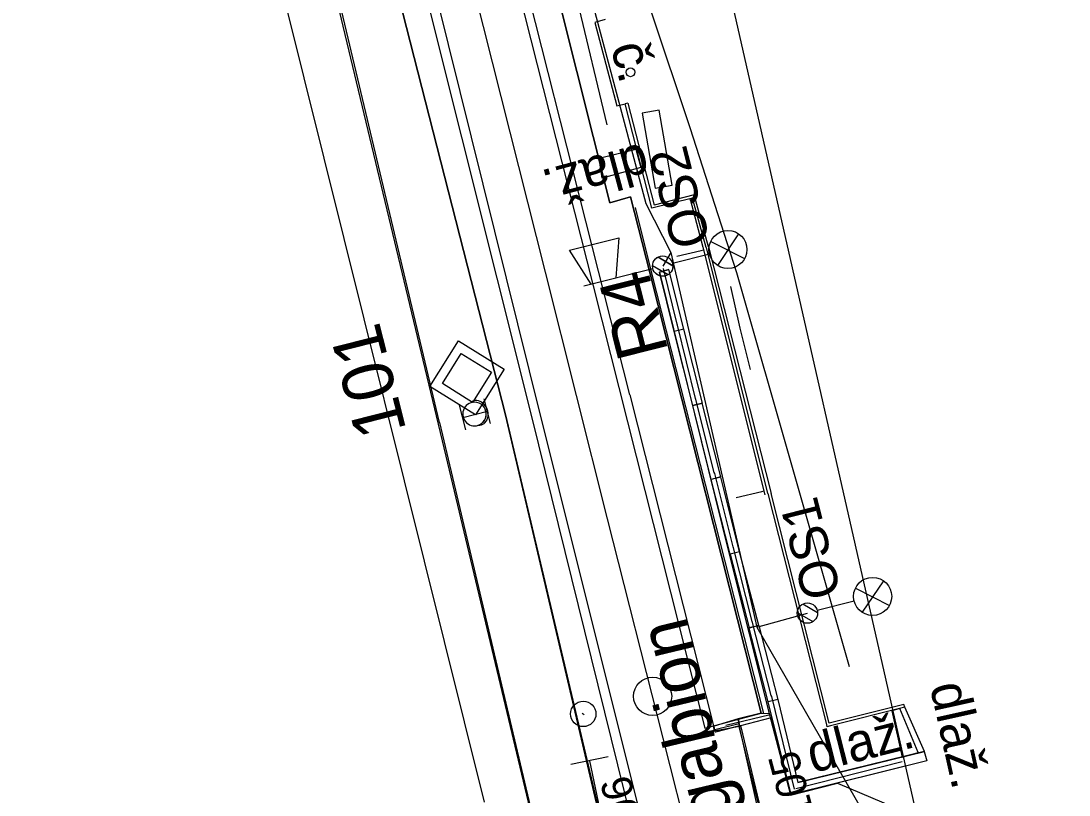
# Model space of a CAD drawing. Extents: x -754679 to -754173, y -1169241 to -1168288.
# Drawn here: x -754414.28 to -754373.05, y -1168944.54 to -1168914.1 of the extents above; entities that cross this region are included whole.
import ezdxf

# ---------------------------------------------------------------- set-up
doc = ezdxf.new("R2010")
doc.units = 0
for name, color, linetype in [('Vrstva 1', 7, 'Continuous'), ('Vrstva 11', 7, 'Continuous'), ('Vrstva 12', 7, 'Continuous'), ('Vrstva 13', 7, 'Continuous'), ('Vrstva 14', 7, 'Continuous'), ('Vrstva 16', 7, 'Continuous'), ('Vrstva 17', 7, 'Continuous'), ('Vrstva 23', 7, 'Continuous'), ('Vrstva 25', 7, 'Continuous'), ('Vrstva 31', 7, 'Continuous'), ('Vrstva 33', 7, 'Continuous'), ('Vrstva 4', 7, 'Continuous'), ('Vrstva 43', 7, 'Continuous'), ('Vrstva 49', 7, 'Continuous'), ('Vrstva 51', 7, 'Continuous'), ('Vrstva 53', 7, 'Continuous'), ('Vrstva 59', 7, 'Continuous'), ('Vrstva 6', 7, 'Continuous'), ('Vrstva 60', 7, 'Continuous'), ('Vrstva 7', 7, 'Continuous')]:
    doc.layers.add(name, color=color, linetype=linetype)

msp = doc.modelspace()

# ---------------------------------------------------------------- linework, layer by layer
at = {"layer": 'Vrstva 1'}
msp.add_lwpolyline([(-754384.656, -1168959.571), (-754385.936, -1168954.491), (-754386.734, -1168951.322), (-754387.865, -1168946.893), (-754387.928, -1168946.598), (-754389.016, -1168942.293), (-754391.2, -1168933.67), (-754393.647, -1168923.979), (-754396.084, -1168914.315), (-754398.294, -1168905.574)], dxfattribs=at)
at = {"layer": 'Vrstva 11'}
for p, q in [((-754395.81, -1168929.924), (-754396.055, -1168928.955)), ((-754396.779, -1168930.169), (-754397.024, -1168929.2)), ((-754396.902, -1168929.685), (-754395.932, -1168929.439))]:
    msp.add_line(p, q, dxfattribs=at)
at = {"layer": 'Vrstva 12'}
for p, q in [((-754396.521, -1168929.047), (-754396.519, -1168929.099)), ((-754395.985, -1168929.451), (-754395.912, -1168929.468)), ((-754396.315, -1168930.002), (-754396.285, -1168929.991))]:
    msp.add_line(p, q, dxfattribs=at)
for centre, major_axis, ratio, start_param, end_param in [((-754396.437, -1168929.555), (-0.102, 0.452), 0.999997, 6.240007, 10.999586), ((-754396.328, -1168929.506), (-0.199, 0.457), 0.826527, 2.759103, 6.267517), ((-754396.437, -1168929.555), (-0.102, 0.452), 0.999997, 3.184771, 6.240007)]:
    msp.add_ellipse(centre, major_axis=major_axis, ratio=ratio, start_param=start_param, end_param=end_param, dxfattribs=at)
at = {"layer": 'Vrstva 13'}
for p, q in [((-754388.795, -1168923.864), (-754389.165, -1168923.968)), ((-754388.582, -1168926.306), (-754389.165, -1168923.968)), ((-754389.165, -1168923.968), (-754389.161, -1168923.973)), ((-754389.161, -1168923.973), (-754388.795, -1168923.864)), ((-754389.161, -1168923.973), (-754386.419, -1168935.058)), ((-754388.209, -1168926.212), (-754388.795, -1168923.864)), ((-754388.795, -1168923.864), (-754388.795, -1168923.864)), ((-754388.209, -1168926.212), (-754388.582, -1168926.306)), ((-754388.207, -1168926.214), (-754388.582, -1168926.307)), ((-754388.582, -1168926.307), (-754388.582, -1168926.306)), ((-754387.853, -1168929.212), (-754388.582, -1168926.307)), ((-754388.207, -1168926.214), (-754388.209, -1168926.212)), ((-754387.475, -1168929.122), (-754388.207, -1168926.214)), ((-754387.475, -1168929.122), (-754387.853, -1168929.212)), ((-754387.853, -1168929.212), (-754387.481, -1168929.123)), ((-754387.481, -1168929.123), (-754387.475, -1168929.122)), ((-754386.748, -1168932.026), (-754387.481, -1168929.123)), ((-754387.123, -1168932.124), (-754387.853, -1168929.212)), ((-754387.853, -1168929.212), (-754387.853, -1168929.212)), ((-754386.748, -1168932.026), (-754387.123, -1168932.124)), ((-754386.75, -1168932.032), (-754387.122, -1168932.123)), ((-754386.75, -1168932.032), (-754386.748, -1168932.026)), ((-754386.01, -1168934.971), (-754386.75, -1168932.032)), ((-754387.122, -1168932.123), (-754387.123, -1168932.124)), ((-754386.387, -1168935.069), (-754387.122, -1168932.123)), ((-754386.419, -1168935.058), (-754384.844, -1168941.33)), ((-754386.009, -1168934.97), (-754386.387, -1168935.07)), ((-754386.01, -1168934.971), (-754386.387, -1168935.069)), ((-754386.387, -1168935.07), (-754386.387, -1168935.069)), ((-754386.387, -1168935.07), (-754385.634, -1168937.967)), ((-754386.009, -1168934.97), (-754386.01, -1168934.971)), ((-754385.256, -1168937.865), (-754386.009, -1168934.97)), ((-754385.256, -1168937.865), (-754385.634, -1168937.967)), ((-754385.631, -1168937.968), (-754385.634, -1168937.967)), ((-754385.256, -1168937.866), (-754385.631, -1168937.968)), ((-754384.889, -1168940.869), (-754385.631, -1168937.968)), ((-754385.256, -1168937.866), (-754385.256, -1168937.865)), ((-754385.256, -1168937.866), (-754384.511, -1168940.778)), ((-754384.51, -1168940.78), (-754384.892, -1168940.869)), ((-754383.981, -1168944.518), (-754384.892, -1168940.869)), ((-754384.892, -1168940.869), (-754384.889, -1168940.869)), ((-754384.511, -1168940.778), (-754384.889, -1168940.869)), ((-754384.51, -1168940.78), (-754384.511, -1168940.778)), ((-754384.511, -1168940.778), (-754383.714, -1168944.039)), ((-754384.51, -1168940.78), (-754383.714, -1168944.04)), ((-754386.071, -1168941.545), (-754387.015, -1168941.827)), ((-754386.008, -1168941.815), (-754386.071, -1168941.545)), ((-754385.963, -1168941.8), (-754384.759, -1168941.493)), ((-754384.844, -1168941.33), (-754384.011, -1168944.533)), ((-754384.759, -1168941.493), (-754384.006, -1168944.538)), ((-754386.97, -1168942.062), (-754387.015, -1168941.827)), ((-754386.027, -1168941.732), (-754386.979, -1168941.973)), ((-754386.008, -1168941.815), (-754386.97, -1168942.062)), ((-754386.027, -1168941.731), (-754386.027, -1168941.732)), ((-754386.007, -1168941.817), (-754386.027, -1168941.732)), ((-754386.023, -1168941.847), (-754385.963, -1168941.8)), ((-754385.064, -1168945.684), (-754386.023, -1168941.847)), ((-754386.008, -1168941.815), (-754386.007, -1168941.817)), ((-754385.032, -1168945.69), (-754385.963, -1168941.8)), ((-754386.96, -1168942.06), (-754386.979, -1168941.973)), ((-754378.65, -1168943.193), (-754384.011, -1168944.533)), ((-754378.643, -1168943.195), (-754383.981, -1168944.518)), ((-754383.714, -1168944.039), (-754378.74, -1168942.822)), ((-754378.748, -1168942.827), (-754383.714, -1168944.04)), ((-754378.748, -1168942.827), (-754378.74, -1168942.822)), ((-754378.748, -1168942.827), (-754378.643, -1168943.195)), ((-754378.643, -1168943.195), (-754378.65, -1168943.193)), ((-754383.714, -1168944.04), (-754383.714, -1168944.039)), ((-754383.981, -1168944.518), (-754384.011, -1168944.533))]:
    msp.add_line(p, q, dxfattribs=at)
for points in [[(-754386.027, -1168941.731), (-754386.982, -1168941.97), (-754386.979, -1168941.973)], [(-754386.007, -1168941.817), (-754386.96, -1168942.06), (-754386.97, -1168942.062)]]:
    msp.add_lwpolyline(points, dxfattribs=at)
at = {"layer": 'Vrstva 14'}
for p, q in [((-754391.113, -1168921.242), (-754393.063, -1168913.475)), ((-754390.299, -1168921.015), (-754391.113, -1168921.242)), ((-754389.528, -1168924.038), (-754390.299, -1168921.015)), ((-754385.162, -1168941.315), (-754389.528, -1168924.038)), ((-754387.375, -1168941.909), (-754385.162, -1168941.315))]:
    msp.add_line(p, q, dxfattribs=at)
msp.add_lwpolyline([(-754414.276, -1168835.483), (-754412.566, -1168842.248), (-754407.917, -1168860.63), (-754403.513, -1168878.067), (-754399.115, -1168895.474), (-754395.207, -1168910.943), (-754391.772, -1168924.511), (-754387.375, -1168941.909)], dxfattribs=at)
at = {"layer": 'Vrstva 16'}
for p, q in [((-754402.14, -1168902.474), (-754395.222, -1168929.578)), ((-754397.82, -1168929.888), (-754404.14, -1168903.209)), ((-754390.209, -1168950.962), (-754395.222, -1168929.578)), ((-754397.82, -1168929.888), (-754393.322, -1168948.872))]:
    msp.add_line(p, q, dxfattribs=at)
msp.add_lwpolyline([(-754391.54, -1168919.494), (-754390.097, -1168919.138), (-754389.895, -1168919.863), (-754391.413, -1168920.273), (-754391.54, -1168919.494)], dxfattribs=at)
at = {"layer": 'Vrstva 17'}
for p, q in [((-754384.808, -1168941.38), (-754386.547, -1168941.8)), ((-754379.619, -1168943.23), (-754383.796, -1168944.293))]:
    msp.add_line(p, q, dxfattribs=at)
msp.add_lwpolyline([(-754383.844, -1168944.301), (-754384.743, -1168940.667), (-754384.765, -1168940.627), (-754385.496, -1168937.745), (-754385.514, -1168937.714), (-754386.249, -1168934.81), (-754386.265, -1168934.776), (-754386.989, -1168931.888), (-754387.01, -1168931.853), (-754387.726, -1168928.979), (-754387.745, -1168928.942), (-754388.446, -1168926.057), (-754388.467, -1168926.021), (-754388.997, -1168923.827)], dxfattribs=at)
at = {"layer": 'Vrstva 23'}
msp.add_line((-754391.701, -1168914.153), (-754390.842, -1168917.432), dxfattribs=at)
for points in [[(-754381.681, -1168939.489), (-754386.122, -1168924.006), (-754387.953, -1168918.303), (-754395.607, -1168895.383), (-754402.869, -1168866.173)], [(-754393.344, -1168948.888), (-754397.546, -1168931.205), (-754401.742, -1168913.695), (-754408.583, -1168884.482)], [(-754386.365, -1168924.542), (-754385.996, -1168926.171), (-754385.598, -1168927.803)]]:
    msp.add_lwpolyline(points, dxfattribs=at)
msp.add_lwpolyline([(-754389.177, -1168917.603), (-754389.843, -1168917.719), (-754389.331, -1168920.671), (-754388.665, -1168920.555)], close=True, dxfattribs=at)
at = {"layer": 'Vrstva 25'}
for p, q in [((-754386.047, -1168922.471), (-754386.881, -1168923.707)), ((-754387.138, -1168922.762), (-754385.811, -1168923.442)), ((-754389.208, -1168923.377), (-754388.638, -1168923.717)), ((-754387.193, -1168923.27), (-754388.647, -1168923.637)), ((-754389.43, -1168923.71), (-754388.823, -1168924.072)), ((-754380.356, -1168936.113), (-754381.19, -1168937.349)), ((-754381.448, -1168936.405), (-754380.12, -1168937.083)), ((-754383.517, -1168937.022), (-754382.947, -1168937.361)), ((-754381.502, -1168936.913), (-754382.956, -1168937.281)), ((-754383.739, -1168937.354), (-754383.132, -1168937.716))]:
    msp.add_line(p, q, dxfattribs=at)
for points in [[(-754392.606, -1168910.34), (-754389.7, -1168921.276), (-754388.719, -1168923.201), (-754389.035, -1168923.735)], [(-754388.719, -1168923.201), (-754385.337, -1168937.932), (-754383.344, -1168937.379)], [(-754385.337, -1168937.932), (-754380.924, -1168945.594), (-754378.67, -1168951.057), (-754378.525, -1168951.376)]]:
    msp.add_lwpolyline(points, dxfattribs=at)
for centre, radius in [((-754386.468, -1168923.084), 0.749), ((-754389.035, -1168923.735), 0.4), ((-754380.777, -1168936.726), 0.749), ((-754383.344, -1168937.379), 0.4)]:
    msp.add_circle(centre, radius, dxfattribs=at)
at = {"layer": 'Vrstva 31'}
for points in [[(-754392.606, -1168910.34), (-754389.7, -1168921.276), (-754388.719, -1168923.201), (-754389.035, -1168923.735)], [(-754388.719, -1168923.201), (-754385.337, -1168937.932), (-754380.924, -1168945.594), (-754378.67, -1168951.057), (-754378.525, -1168951.376)]]:
    msp.add_lwpolyline(points, dxfattribs=at)
at = {"layer": 'Vrstva 33'}
for p, q in [((-754388.637, -1168923.732), (-754389.222, -1168923.383)), ((-754392.134, -1168924.517), (-754389.423, -1168923.833)), ((-754388.834, -1168924.08), (-754389.432, -1168923.724))]:
    msp.add_line(p, q, dxfattribs=at)
msp.add_lwpolyline([(-754391.843, -1168924.444), (-754392.695, -1168923.112), (-754390.756, -1168922.622), (-754390.873, -1168924.199)], dxfattribs=at)
msp.add_circle((-754389.035, -1168923.735), 0.401, dxfattribs=at)
at = {"layer": 'Vrstva 4'}
for p, q in [((-754390.328, -1168928.8), (-754397.327, -1168901.139)), ((-754401.081, -1168902.211), (-754394.179, -1168929.708)), ((-754393.809, -1168929.698), (-754400.667, -1168902.072)), ((-754395.222, -1168929.578), (-754402.14, -1168902.474)), ((-754390.328, -1168928.8), (-754387.041, -1168941.818)), ((-754395.222, -1168929.578), (-754390.121, -1168951.135)), ((-754394.179, -1168929.708), (-754388.744, -1168951.72)), ((-754388.295, -1168951.767), (-754393.809, -1168929.698)), ((-754387.041, -1168941.818), (-754387.022, -1168942.028)), ((-754386.014, -1168941.847), (-754387.022, -1168942.028)), ((-754385.154, -1168945.699), (-754386.014, -1168941.847))]:
    msp.add_line(p, q, dxfattribs=at)
at = {"layer": 'Vrstva 43'}
msp.add_line((-754392.405, -1168913.302), (-754391.226, -1168918.175), dxfattribs=at)
for points in [[(-754387.959, -1168921.11), (-754387.458, -1168922.996), (-754385.012, -1168932.727)], [(-754390.117, -1168921.433), (-754389.474, -1168924.019), (-754385.071, -1168941.331)], [(-754388.48, -1168923.343), (-754387.515, -1168923.117), (-754387.432, -1168923.098)], [(-754386.146, -1168932.839), (-754385.129, -1168932.595), (-754385.05, -1168932.576)]]:
    msp.add_lwpolyline(points, dxfattribs=at)
at = {"layer": 'Vrstva 49'}
msp.add_lwpolyline([(-754384.006, -1168944.538), (-754382.158, -1168944.067), (-754378.6, -1168945.58), (-754377.58, -1168949.01), (-754375.672, -1168950.079), (-754373.052, -1168951.324)], dxfattribs=at)
at = {"layer": 'Vrstva 51'}
for p, q in [((-754391.3, -1168914.039), (-754391.701, -1168914.153)), ((-754391.701, -1168914.153), (-754390.842, -1168917.432)), ((-754390.842, -1168917.432), (-754390.515, -1168917.354)), ((-754390.409, -1168917.33), (-754390.515, -1168917.354)), ((-754389.458, -1168921.46), (-754390.515, -1168917.354)), ((-754390.409, -1168917.33), (-754389.375, -1168921.333)), ((-754387.792, -1168920.929), (-754389.375, -1168921.333)), ((-754387.227, -1168922.984), (-754387.792, -1168920.929)), ((-754387.86, -1168921.064), (-754389.458, -1168921.46)), ((-754387.326, -1168923.005), (-754387.86, -1168921.064)), ((-754387.318, -1168923.01), (-754387.326, -1168923.005)), ((-754387.227, -1168922.984), (-754384.774, -1168932.673)), ((-754384.905, -1168932.683), (-754387.318, -1168923.01)), ((-754382.483, -1168941.706), (-754384.774, -1168932.673)), ((-754379.545, -1168940.978), (-754382.483, -1168941.706)), ((-754379.515, -1168941.074), (-754379.545, -1168940.978)), ((-754378.74, -1168942.822), (-754379.515, -1168941.074)), ((-754385.162, -1168941.315), (-754386.071, -1168941.545)), ((-754386.071, -1168941.545), (-754386.008, -1168941.815)), ((-754385.162, -1168941.315), (-754384.844, -1168941.33))]:
    msp.add_line(p, q, dxfattribs=at)
for points in [[(-754412.047, -1168834.907), (-754410.208, -1168842.187), (-754405.698, -1168860.083), (-754401.304, -1168877.422), (-754396.888, -1168895.004), (-754392.927, -1168910.532), (-754392.287, -1168913.272), (-754393.063, -1168913.475), (-754391.113, -1168921.242), (-754390.299, -1168921.015), (-754389.528, -1168924.038), (-754385.162, -1168941.315)], [(-754384.905, -1168932.683), (-754382.598, -1168941.756), (-754382.574, -1168941.851)], [(-754379.515, -1168941.074), (-754382.438, -1168941.816), (-754382.574, -1168941.851)], [(-754379.618, -1168943.048), (-754378.986, -1168942.865), (-754379.706, -1168941.132), (-754380.023, -1168941.222), (-754379.618, -1168943.048)]]:
    msp.add_lwpolyline(points, dxfattribs=at)
at = {"layer": 'Vrstva 53'}
for p, q in [((-754396.56, -1168868.29), (-754379.05, -1168945.33)), ((-754396.05, -1168944.82), (-754406.43, -1168903.09))]:
    msp.add_line(p, q, dxfattribs=at)
at = {"layer": 'Vrstva 59'}
msp.add_circle((-754390.301, -1168916.112), 0.175, dxfattribs=at)
at = {"layer": 'Vrstva 6'}
for points in [[(-754396.401, -1168929.589), (-754398.19, -1168928.47), (-754397.068, -1168926.676), (-754395.276, -1168927.791), (-754396.401, -1168929.589)], [(-754397.691, -1168928.355), (-754396.955, -1168927.167), (-754395.763, -1168927.903), (-754396.513, -1168929.102), (-754397.691, -1168928.355)]]:
    msp.add_lwpolyline(points, dxfattribs=at)
at = {"layer": 'Vrstva 7'}
for p, q in [((-754392.201, -1168941.318), (-754392.117, -1168941.372)), ((-754391.175, -1168943.032), (-754392.643, -1168943.338))]:
    msp.add_line(p, q, dxfattribs=at)
msp.add_lwpolyline([(-754391.909, -1168943.185), (-754391.296, -1168946.122), (-754393.009, -1168946.479), (-754392.499, -1168948.927), (-754389.072, -1168948.212), (-754389.583, -1168945.764), (-754391.296, -1168946.122)], dxfattribs=at)
for centre, radius in [((-754389.431, -1168940.654), 0.75), ((-754392.159, -1168941.345), 0.5)]:
    msp.add_circle(centre, radius, dxfattribs=at)

# ---------------------------------------------------------------- texts
at = {"layer": 'Vrstva 11'}
msp.add_text('101', height=2, rotation=104.1967, dxfattribs=at).set_placement((-754399.109, -1168930.195))
at = {"layer": 'Vrstva 13'}
msp.add_text('gabion', height=2, rotation=103.4595, dxfattribs=at).set_placement((-754386.254, -1168945.261))
at = {"layer": 'Vrstva 16'}
msp.add_text('dlaž.', height=1.5, rotation=195.1145, dxfattribs=at).set_placement((-754389.798, -1168918.889))
at = {"layer": 'Vrstva 23'}
msp.add_text('č.', height=1.5, rotation=284.6799, dxfattribs=at).set_placement((-754391.088, -1168915.114))
at = {"layer": 'Vrstva 25'}
for s, rotation, p in [('OS2', 104.1711, (-754387.15, -1168922.805)), ('OS1', 104.2128, (-754382.002, -1168936.617))]:
    msp.add_text(s, height=1.5, rotation=rotation, dxfattribs=at).set_placement(p)
at = {"layer": 'Vrstva 33'}
msp.add_text('R4', height=2, rotation=104.1711, dxfattribs=at).set_placement((-754388.803, -1168927.09))
at = {"layer": 'Vrstva 51'}
for rotation, p in [(282.5055, (-754378.53, -1168940.254)), (14.2436, (-754383.143, -1168943.676))]:
    msp.add_text('dlaž.', height=1.5, rotation=rotation, dxfattribs=at).set_placement(p)
at = {"layer": 'Vrstva 60'}
for s, p in [('105', (-754383.059, -1168945.298)), ('106', (-754389.659, -1168946.28))]:
    msp.add_text(s, height=1.2, rotation=105, dxfattribs=at).set_placement(p)

doc.saveas('drawing.dxf')
